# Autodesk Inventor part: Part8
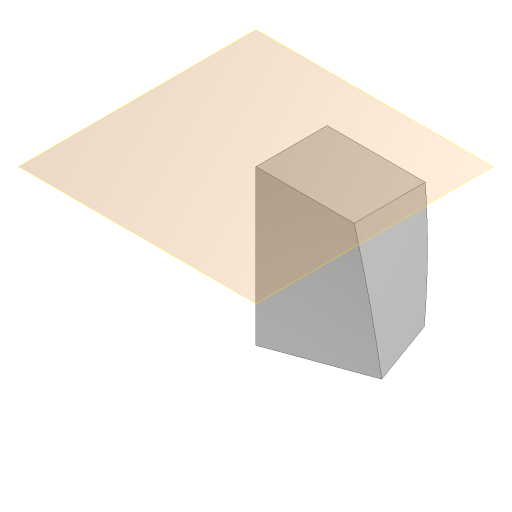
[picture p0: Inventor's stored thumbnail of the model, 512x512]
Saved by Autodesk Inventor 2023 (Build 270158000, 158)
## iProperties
Created: 2015-07
Part Number: Part8
Material: Generic
Document SubType Name: Modeling
Designer: Sandeep
Density: 1 g/cm^3
Appearance: Default
Author: Sandeep
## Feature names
1. Sweep1
## Parameters: d0 = 0, d1 = -20 deg
